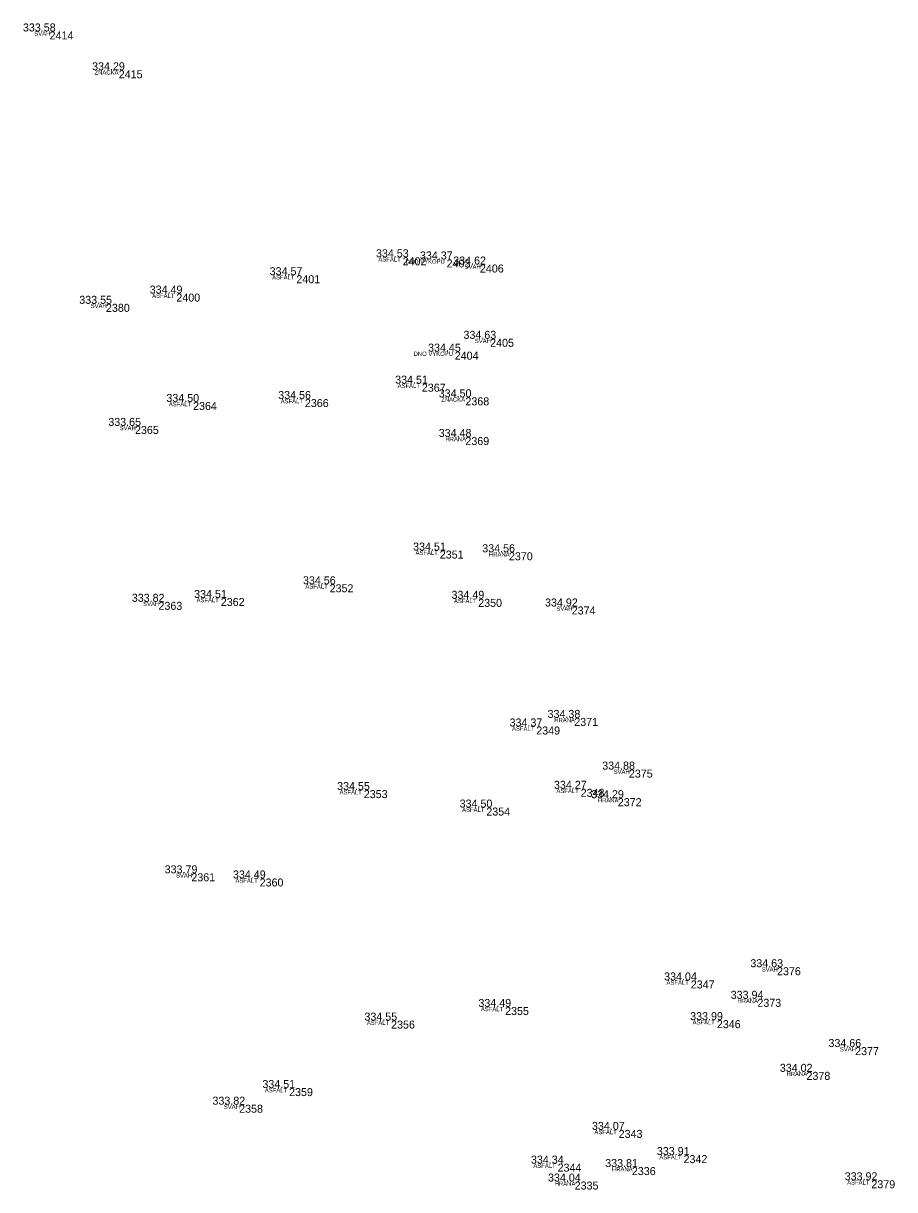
# Model space of a CAD drawing. Extents: x -597865 to -597551, y -1151663 to -1149883.
# Drawn here: x -597671.43 to -597651.01, y -1149937.64 to -1149910.32 of the extents above; entities that cross this region are included whole.
import ezdxf

# ---------------------------------------------------------------- set-up
doc = ezdxf.new("R2010")
doc.units = 0
for name, color, linetype in [('Vrstva 11', 7, 'Continuous'), ('Vrstva 12', 7, 'Continuous'), ('Vrstva 13', 7, 'Continuous'), ('Vrstva 14', 7, 'Continuous')]:
    doc.layers.add(name, color=color, linetype=linetype)

msp = doc.modelspace()

# ---------------------------------------------------------------- linework, layer by layer
at = {"layer": 'Vrstva 11'}
for p, q in [((-597670.81, -1149910.51), (-597670.81, -1149910.51)), ((-597669.19, -1149911.42), (-597669.19, -1149911.42)), ((-597662.54, -1149915.8), (-597662.54, -1149915.8)), ((-597661.51, -1149915.85), (-597661.51, -1149915.85)), ((-597660.73, -1149915.97), (-597660.73, -1149915.97)), ((-597665.03, -1149916.22), (-597665.03, -1149916.22)), ((-597669.49, -1149916.89), (-597669.49, -1149916.89)), ((-597667.84, -1149916.65), (-597667.84, -1149916.65)), ((-597660.49, -1149917.71), (-597660.49, -1149917.71)), ((-597661.32, -1149918.01), (-597661.32, -1149918.01)), ((-597662.09, -1149918.76), (-597662.09, -1149918.76)), ((-597661.07, -1149919.08), (-597661.07, -1149919.08)), ((-597667.45, -1149919.19), (-597667.45, -1149919.19)), ((-597664.83, -1149919.12), (-597664.83, -1149919.12)), ((-597668.81, -1149919.75), (-597668.81, -1149919.75)), ((-597661.07, -1149920.01), (-597661.07, -1149920.01)), ((-597661.67, -1149922.67), (-597661.67, -1149922.67)), ((-597660.05, -1149922.71), (-597660.05, -1149922.71)), ((-597664.25, -1149923.46), (-597664.25, -1149923.46)), ((-597668.26, -1149923.87), (-597668.26, -1149923.87)), ((-597666.8, -1149923.78), (-597666.8, -1149923.78)), ((-597660.77, -1149923.8), (-597660.77, -1149923.8)), ((-597658.58, -1149923.98), (-597658.58, -1149923.98)), ((-597658.52, -1149926.59), (-597658.52, -1149926.59)), ((-597659.41, -1149926.79), (-597659.41, -1149926.79)), ((-597657.24, -1149927.8), (-597657.24, -1149927.8)), ((-597663.45, -1149928.28), (-597663.45, -1149928.28)), ((-597658.37, -1149928.25), (-597658.37, -1149928.25)), ((-597657.5, -1149928.47), (-597657.5, -1149928.47)), ((-597660.58, -1149928.69), (-597660.58, -1149928.69)), ((-597667.49, -1149930.23), (-597667.49, -1149930.23)), ((-597665.89, -1149930.35), (-597665.89, -1149930.35)), ((-597653.77, -1149932.43), (-597653.77, -1149932.43)), ((-597655.79, -1149932.74), (-597655.79, -1149932.74)), ((-597654.23, -1149933.17), (-597654.23, -1149933.17)), ((-597660.14, -1149933.36), (-597660.14, -1149933.36)), ((-597662.81, -1149933.68), (-597662.81, -1149933.68)), ((-597655.18, -1149933.67), (-597655.18, -1149933.67)), ((-597651.94, -1149934.3), (-597651.94, -1149934.3)), ((-597653.08, -1149934.88), (-597653.08, -1149934.88)), ((-597665.2, -1149935.26), (-597665.2, -1149935.26)), ((-597666.37, -1149935.65), (-597666.37, -1149935.65)), ((-597657.48, -1149936.24), (-597657.48, -1149936.24)), ((-597655.96, -1149936.83), (-597655.96, -1149936.83)), ((-597658.91, -1149937.03), (-597658.91, -1149937.03)), ((-597657.17, -1149937.11), (-597657.17, -1149937.11)), ((-597658.51, -1149937.45), (-597658.51, -1149937.45)), ((-597651.56, -1149937.42), (-597651.56, -1149937.42))]:
    msp.add_line(p, q, dxfattribs=at)

# ---------------------------------------------------------------- texts
at = {"layer": 'Vrstva 12'}
for s, p in [('333.58 ', (-597671.435, -1149910.51)), ('334.29 ', (-597669.815, -1149911.42)), ('334.53 ', (-597663.165, -1149915.8)), ('334.37 ', (-597662.135, -1149915.85)), ('334.62 ', (-597661.355, -1149915.97)), ('334.57 ', (-597665.655, -1149916.22)), ('334.49 ', (-597668.465, -1149916.65)), ('333.55 ', (-597670.115, -1149916.89)), ('334.63 ', (-597661.115, -1149917.71)), ('334.45 ', (-597661.945, -1149918.01)), ('334.51 ', (-597662.715, -1149918.76)), ('334.50 ', (-597668.075, -1149919.19)), ('334.56 ', (-597665.455, -1149919.12)), ('334.50 ', (-597661.695, -1149919.08)), ('333.65 ', (-597669.435, -1149919.75)), ('334.48 ', (-597661.695, -1149920.01)), ('334.51 ', (-597662.295, -1149922.67)), ('334.56 ', (-597660.675, -1149922.71)), ('334.56 ', (-597664.875, -1149923.46)), ('333.82 ', (-597668.885, -1149923.87)), ('334.51 ', (-597667.425, -1149923.78)), ('334.49 ', (-597661.395, -1149923.8)), ('334.92 ', (-597659.205, -1149923.98)), ('334.38 ', (-597659.145, -1149926.59)), ('334.37 ', (-597660.035, -1149926.79)), ('334.88 ', (-597657.865, -1149927.8)), ('334.55 ', (-597664.075, -1149928.28)), ('334.27 ', (-597658.995, -1149928.25)), ('334.29 ', (-597658.125, -1149928.47)), ('334.50 ', (-597661.205, -1149928.69)), ('333.79 ', (-597668.115, -1149930.23)), ('334.49 ', (-597666.515, -1149930.35)), ('334.63 ', (-597654.395, -1149932.43)), ('334.04 ', (-597656.415, -1149932.74)), ('333.94 ', (-597654.855, -1149933.17)), ('334.49 ', (-597660.765, -1149933.36)), ('334.55 ', (-597663.435, -1149933.68)), ('333.99 ', (-597655.805, -1149933.67)), ('334.66 ', (-597652.565, -1149934.3)), ('334.02 ', (-597653.705, -1149934.88)), ('334.51 ', (-597665.825, -1149935.26)), ('333.82 ', (-597666.995, -1149935.65)), ('334.07 ', (-597658.105, -1149936.24)), ('334.34 ', (-597659.535, -1149937.03)), ('333.91 ', (-597656.585, -1149936.83)), ('333.81 ', (-597657.795, -1149937.11)), ('334.04 ', (-597659.135, -1149937.45)), ('333.92 ', (-597652.185, -1149937.42))]:
    msp.add_text(s, height=0.1875, dxfattribs=at).set_placement(p)
at = {"layer": 'Vrstva 13'}
for s, p in [('2414', (-597670.81, -1149910.698)), ('2415', (-597669.19, -1149911.607)), ('2402', (-597662.54, -1149915.988)), ('2403', (-597661.51, -1149916.038)), ('2406', (-597660.73, -1149916.157)), ('2401', (-597665.03, -1149916.407)), ('2380', (-597669.49, -1149917.078)), ('2400', (-597667.84, -1149916.838)), ('2405', (-597660.49, -1149917.897)), ('2404', (-597661.32, -1149918.198)), ('2367', (-597662.09, -1149918.948)), ('2368', (-597661.07, -1149919.268)), ('2364', (-597667.45, -1149919.377)), ('2366', (-597664.83, -1149919.308)), ('2365', (-597668.81, -1149919.938)), ('2369', (-597661.07, -1149920.198)), ('2351', (-597661.67, -1149922.857)), ('2370', (-597660.05, -1149922.897)), ('2352', (-597664.25, -1149923.647)), ('2363', (-597668.26, -1149924.058)), ('2362', (-597666.8, -1149923.968)), ('2350', (-597660.77, -1149923.988)), ('2374', (-597658.58, -1149924.167)), ('2371', (-597658.52, -1149926.778)), ('2349', (-597659.41, -1149926.978)), ('2375', (-597657.24, -1149927.988)), ('2353', (-597663.45, -1149928.468)), ('2348', (-597658.37, -1149928.438)), ('2372', (-597657.5, -1149928.657)), ('2354', (-597660.58, -1149928.877)), ('2361', (-597667.49, -1149930.417)), ('2360', (-597665.89, -1149930.538)), ('2376', (-597653.77, -1149932.617)), ('2347', (-597655.79, -1149932.927)), ('2373', (-597654.23, -1149933.357)), ('2355', (-597660.14, -1149933.548)), ('2356', (-597662.81, -1149933.867)), ('2346', (-597655.18, -1149933.857)), ('2377', (-597651.94, -1149934.488)), ('2378', (-597653.08, -1149935.068)), ('2359', (-597665.2, -1149935.448)), ('2358', (-597666.37, -1149935.838)), ('2343', (-597657.48, -1149936.427)), ('2342', (-597655.96, -1149937.018)), ('2344', (-597658.91, -1149937.218)), ('2336', (-597657.17, -1149937.298)), ('2335', (-597658.51, -1149937.637)), ('2379', (-597651.56, -1149937.607))]:
    msp.add_text(s, height=0.1875, dxfattribs=at).set_placement(p)
at = {"layer": 'Vrstva 14'}
for s, p in [('SVAH', (-597671.168, -1149910.61)), ('ZNACKA', (-597669.757, -1149911.52)), ('ASFALT', (-597663.107, -1149915.9)), ('DNO VYKOPU', (-597662.473, -1149915.95)), ('SVAH', (-597661.088, -1149916.07)), ('ASFALT', (-597665.597, -1149916.32)), ('SVAH', (-597669.848, -1149916.99)), ('ASFALT', (-597668.407, -1149916.75)), ('SVAH', (-597660.848, -1149917.81)), ('DNO VYKOPU', (-597662.282, -1149918.11)), ('ASFALT', (-597662.657, -1149918.86)), ('ZNACKA', (-597661.637, -1149919.18)), ('ASFALT', (-597668.017, -1149919.29)), ('ASFALT', (-597665.397, -1149919.22)), ('SVAH', (-597669.168, -1149919.85)), ('HRANA', (-597661.537, -1149920.11)), ('ASFALT', (-597662.237, -1149922.77)), ('HRANA', (-597660.517, -1149922.81)), ('ASFALT', (-597664.817, -1149923.56)), ('SVAH', (-597668.618, -1149923.97)), ('ASFALT', (-597667.367, -1149923.88)), ('ASFALT', (-597661.337, -1149923.9)), ('SVAH', (-597658.938, -1149924.08)), ('HRANA', (-597658.987, -1149926.69)), ('ASFALT', (-597659.977, -1149926.89)), ('SVAH', (-597657.598, -1149927.9)), ('ASFALT', (-597664.017, -1149928.38)), ('ASFALT', (-597658.937, -1149928.35)), ('HRANA', (-597657.967, -1149928.57)), ('ASFALT', (-597661.147, -1149928.79)), ('SVAH', (-597667.848, -1149930.33)), ('ASFALT', (-597666.457, -1149930.45)), ('SVAH', (-597654.128, -1149932.53)), ('ASFALT', (-597656.357, -1149932.84)), ('HRANA', (-597654.697, -1149933.27)), ('ASFALT', (-597660.707, -1149933.46)), ('ASFALT', (-597663.377, -1149933.78)), ('ASFALT', (-597655.747, -1149933.77)), ('SVAH', (-597652.298, -1149934.4)), ('HRANA', (-597653.547, -1149934.98)), ('ASFALT', (-597665.767, -1149935.36)), ('SVAH', (-597666.728, -1149935.75)), ('ASFALT', (-597658.047, -1149936.34)), ('ASFALT', (-597656.527, -1149936.93)), ('ASFALT', (-597659.477, -1149937.13)), ('HRANA', (-597657.637, -1149937.21)), ('HRANA', (-597658.977, -1149937.55)), ('ASFALT', (-597652.127, -1149937.52))]:
    msp.add_text(s, height=0.1, dxfattribs=at).set_placement(p)

doc.saveas('drawing.dxf')
